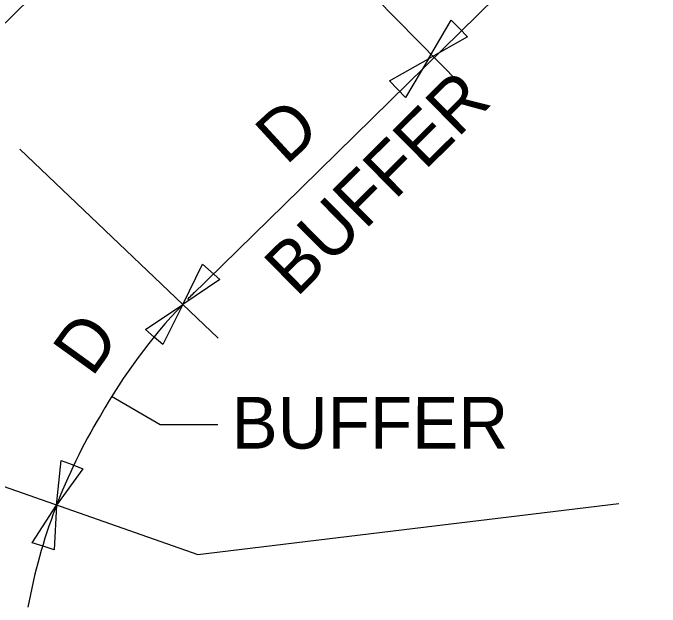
# Model space of a CAD drawing. Extents: x 16735 to 19510, y 5880 to 6929.
# Drawn here: x 16959.8 to 17047.4, y 6368.7 to 6449.1 of the extents above; entities that cross this region are included whole.
import ezdxf

# ---------------------------------------------------------------- set-up
doc = ezdxf.new("R2010")
doc.units = 0
doc.layers.add('BORDER', color=7, linetype='Continuous')
doc.layers.add('TRAFFIC_SIGNS_PR', color=7, linetype='Continuous')

msp = doc.modelspace()

# ---------------------------------------------------------------- linework, layer by layer
at = {"layer": 'BORDER'}
msp.add_line((17374.593, 6855.348), (16953.186, 6442.304), dxfattribs=at)
at = {"layer": 'TRAFFIC_SIGNS_PR'}
for p, q in [((16978.132, 6482.506), (17020.305, 6439.48)), ((17031.972, 6457.916), (16996.478, 6423.127)), ((17016.015, 6442.854), (17019.102, 6448.079)), ((17019.102, 6448.079), (17020.201, 6446.957)), ((17020.201, 6446.957), (17021.301, 6445.836)), ((17021.301, 6445.836), (17016.015, 6442.854)), ((17010.729, 6439.872), (17016.015, 6442.854)), ((17016.015, 6442.854), (17012.928, 6437.629)), ((17011.829, 6438.751), (17010.729, 6439.872)), ((17012.928, 6437.629), (17011.829, 6438.751)), ((16960.712, 6430.626), (16987.559, 6405.074)), ((16996.478, 6423.127), (16983.985, 6410.881)), ((16982.769, 6409.633), (16985.446, 6415.079)), ((16985.446, 6415.079), (16986.628, 6414.045)), ((16986.628, 6414.045), (16987.811, 6413.012)), ((16987.811, 6413.012), (16982.769, 6409.633)), ((16977.727, 6406.254), (16982.769, 6409.633)), ((16982.769, 6409.633), (16980.092, 6404.186)), ((16978.91, 6405.221), (16977.727, 6406.254)), ((16980.092, 6404.186), (16978.91, 6405.221)), ((16979.723, 6393.334), (16973.154, 6397.166)), ((16935.708, 6392.978), (16984.802, 6375.792)), ((16987.524, 6393.334), (16979.723, 6393.334)), ((16965.703, 6382.478), (16966.346, 6388.512)), ((16966.346, 6388.512), (16967.811, 6387.947)), ((16967.811, 6387.947), (16969.277, 6387.383)), ((16969.277, 6387.383), (16965.703, 6382.478)), ((16962.402, 6377.385), (16965.703, 6382.478)), ((16965.703, 6382.478), (16965.391, 6376.417)), ((16984.802, 6375.792), (17041.795, 6382.676)), ((16963.897, 6376.902), (16962.402, 6377.385)), ((16965.391, 6376.417), (16963.897, 6376.902))]:
    msp.add_line(p, q, dxfattribs=at)
for centre, radius, start, end in [((17037.825, 6357.232), 76.007, 134.35623, 135.71324), ((17037.825, 6357.232), 76.007, 136.41535, 150.54462), ((17037.395, 6354.89), 76.817, 148.86564, 169.66186)]:
    msp.add_arc(centre, radius, start, end, dxfattribs=at)

# ---------------------------------------------------------------- texts
for s, rotation, p in [('BUFFER', 44.73328, (16998.174, 6410.488)), ('D', 42.59403, (16996.745, 6428.343)), ('D', 54.19879, (16970.495, 6399.648)), ('BUFFER', 359.98822, (16989.376, 6390.121))]:
    msp.add_text(s, height=7, rotation=rotation, dxfattribs=at).set_placement(p)

doc.saveas('drawing.dxf')
